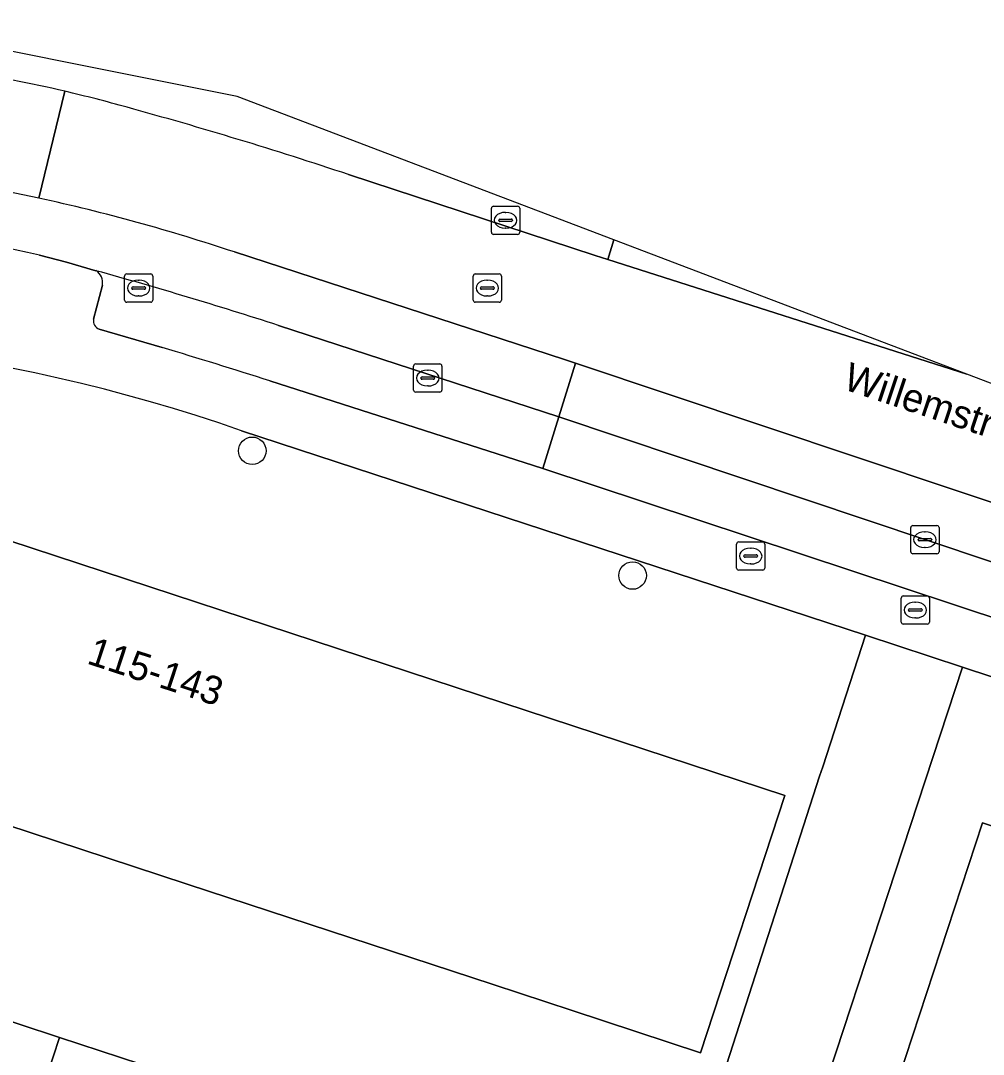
# Model space of a CAD drawing. Extents: x 159960 to 160866, y 382700 to 383354.
# Drawn here: x 160319.72 to 160353.88, y 383315.87 to 383352.54 of the extents above; entities that cross this region are included whole.
import ezdxf

# ---------------------------------------------------------------- set-up
doc = ezdxf.new("R2010")
doc.units = 0
for name, color, linetype in [('IMGEO_Boom', 7, 'Continuous'), ('IMGEO_Brandkraan', 7, 'Continuous'), ('IMGEO_Erf', 7, 'Continuous'), ('IMGEO_Kolk', 7, 'Continuous'), ('IMGEO_Openbare_ruimte_label', 7, 'Continuous'), ('IMGEO_Pand', 7, 'Continuous'), ('IMGEO_Pand_nummerreeks', 7, 'Continuous'), ('IMGEO_Parkeervlak_open', 7, 'Continuous'), ('IMGEO_Rijbaan_lokaal_gesloten', 7, 'Continuous'), ('IMGEO_Rioolput', 7, 'Continuous'), ('IMGEO_Voetpad_open', 7, 'Continuous')]:
    doc.layers.add(name, color=color, linetype=linetype)

msp = doc.modelspace()

# ---------------------------------------------------------------- linework, layer by layer
at = {"layer": 'IMGEO_Boom'}
for centre in [(160327.94, 383337.28), (160341.433, 383332.855)]:
    msp.add_circle(centre, 0.489, dxfattribs=at)
at = {"layer": 'IMGEO_Brandkraan'}
for p, q in [((160345.123, 383333.12), (160345.123, 383333.972)), ((160345.198, 383334.046), (160346.05, 383334.046)), ((160346.124, 383333.972), (160346.124, 383333.12)), ((160345.382, 383333.54), (160345.382, 383333.552)), ((160345.425, 383333.589), (160345.823, 383333.589)), ((160345.611, 383333.826), (160345.636, 383333.826)), ((160345.866, 383333.552), (160345.866, 383333.54)), ((160345.82, 383333.503), (160345.422, 383333.503)), ((160345.634, 383333.266), (160345.609, 383333.266)), ((160346.05, 383333.046), (160345.198, 383333.046)), ((160351.038, 383332.13), (160351.89, 383332.13)), ((160350.963, 383331.204), (160350.963, 383332.056)), ((160351.451, 383331.91), (160351.476, 383331.91)), ((160351.964, 383332.056), (160351.964, 383331.204)), ((160351.222, 383331.624), (160351.222, 383331.636)), ((160351.66, 383331.587), (160351.262, 383331.587)), ((160351.265, 383331.673), (160351.663, 383331.673)), ((160351.474, 383331.35), (160351.449, 383331.35)), ((160351.706, 383331.636), (160351.706, 383331.624)), ((160351.89, 383331.13), (160351.038, 383331.13))]:
    msp.add_line(p, q, dxfattribs=at)
for points in [[(160345.123, 383333.12), (160345.123, 383333.972)], [(160345.198, 383334.046), (160346.05, 383334.046)], [(160346.124, 383333.972), (160346.124, 383333.12)], [(160346.05, 383333.046), (160345.198, 383333.046)], [(160351.038, 383332.13), (160351.89, 383332.13)], [(160350.963, 383331.204), (160350.963, 383332.056)], [(160351.964, 383332.056), (160351.964, 383331.204)], [(160351.89, 383331.13), (160351.038, 383331.13)]]:
    msp.add_lwpolyline(points, dxfattribs=at)
for centre, radius, start, end in [((160345.2, 383333.97), 0.0765, 91.552, 178.448), ((160345.2, 383333.97), 0.0765, 91.552, 178.448), ((160346.048, 383333.97), 0.0765, 1.552, 88.448), ((160346.048, 383333.97), 0.0765, 1.552, 88.448), ((160345.422, 383333.549), 0.0403, 85.8775, 175.7526), ((160345.419, 383333.539), 0.0366, 178.938, 274.7102), ((160345.823, 383333.546), 0.043, 264.8664, 352.4533), ((160345.827, 383333.551), 0.0386, 1.7309, 96.639), ((160345.2, 383333.122), 0.0765, 181.552, 268.448), ((160345.2, 383333.122), 0.0765, 181.552, 268.448), ((160346.048, 383333.122), 0.0765, 271.552, 358.448), ((160346.048, 383333.122), 0.0765, 271.552, 358.448), ((160351.04, 383332.054), 0.0765, 91.552, 178.448), ((160351.04, 383332.054), 0.0765, 91.552, 178.448), ((160351.888, 383332.054), 0.0765, 1.552, 88.448), ((160351.888, 383332.054), 0.0765, 1.552, 88.448), ((160351.262, 383331.633), 0.0403, 85.8775, 175.7526), ((160351.259, 383331.623), 0.0366, 178.938, 274.7102), ((160351.663, 383331.63), 0.043, 264.8664, 352.4533), ((160351.667, 383331.635), 0.0386, 1.7309, 96.639), ((160351.04, 383331.206), 0.0765, 181.552, 268.448), ((160351.04, 383331.206), 0.0765, 181.552, 268.448), ((160351.888, 383331.206), 0.0765, 271.552, 358.448), ((160351.888, 383331.206), 0.0765, 271.552, 358.448)]:
    msp.add_arc(centre, radius, start, end, dxfattribs=at)
for centre, major_axis, ratio, start_param, end_param in [((160345.61, 383333.546), (-0.387, 0.002), 0.722429, 4.712389, 7.853982), ((160345.635, 383333.546), (-0.39, 0.002), 0.717154, 1.570796, 4.712389), ((160351.45, 383331.63), (-0.387, 0.002), 0.722429, 4.712389, 7.853982), ((160351.475, 383331.63), (-0.39, 0.002), 0.717154, 1.570796, 4.712389)]:
    msp.add_ellipse(centre, major_axis=major_axis, ratio=ratio, start_param=start_param, end_param=end_param, dxfattribs=at)
at = {"layer": 'IMGEO_Erf'}
for points in [[(160294.643, 383340.108), (160295.522, 383338.01), (160299.076, 383339.507), (160299.604, 383338.3), (160304.591, 383340.38), (160306.367, 383339.797), (160305.935, 383338.483), (160346.836, 383325.049), (160343.838, 383315.922), (160339.287, 383317.418), (160336.483, 383318.339), (160325.633, 383321.902)], [(160318.229, 383317.411), (160321.105, 383316.464), (160323.98, 383315.516), (160323.304, 383313.464), (160331.274, 383310.851), (160331.957, 383312.922), (160334.773, 383311.994), (160337.589, 383311.067), (160336.906, 383308.995), (160342.152, 383307.387), (160348.068, 383325.735), (160348.178, 383326.072), (160349.696, 383330.734), (160327.562, 383337.994)], [(160378.836, 383321.134), (160353.138, 383329.606), (160345.489, 383306.308), (160342.824, 383298.191), (160357.034, 383293.635)], [(160325.633, 383321.902), (160322.789, 383322.836), (160311.959, 383326.393)], [(160358.663, 383304.22), (160352.531, 383306.232), (160354.223, 383311.389), (160350.128, 383312.732), (160353.853, 383324.085), (160359.803, 383322.132)]]:
    msp.add_lwpolyline(points, dxfattribs=at)
msp.add_arc((160307.282, 383279.559), 61.854, 70.86077, 95.92134, dxfattribs=at)
at = {"layer": 'IMGEO_Kolk'}
for p, q in [((160323.408, 383342.627), (160323.408, 383343.479)), ((160323.483, 383343.553), (160324.335, 383343.553)), ((160324.409, 383343.479), (160324.409, 383342.627)), ((160323.71, 383343.096), (160324.108, 383343.096)), ((160323.896, 383343.333), (160323.921, 383343.333)), ((160323.667, 383343.047), (160323.667, 383343.059)), ((160324.105, 383343.01), (160323.707, 383343.01)), ((160323.919, 383342.773), (160323.894, 383342.773)), ((160324.151, 383343.059), (160324.151, 383343.047)), ((160324.335, 383342.553), (160323.483, 383342.553)), ((160333.665, 383339.435), (160333.665, 383340.287)), ((160333.74, 383340.361), (160334.592, 383340.361)), ((160334.153, 383340.141), (160334.178, 383340.141)), ((160334.666, 383340.287), (160334.666, 383339.435)), ((160333.924, 383339.855), (160333.924, 383339.867)), ((160334.362, 383339.818), (160333.964, 383339.818)), ((160333.967, 383339.904), (160334.365, 383339.904)), ((160334.408, 383339.867), (160334.408, 383339.855)), ((160334.176, 383339.581), (160334.151, 383339.581)), ((160334.592, 383339.361), (160333.74, 383339.361)), ((160351.304, 383333.701), (160351.304, 383334.553)), ((160351.379, 383334.627), (160352.231, 383334.627)), ((160351.792, 383334.407), (160351.817, 383334.407)), ((160352.305, 383334.553), (160352.305, 383333.701)), ((160351.563, 383334.121), (160351.563, 383334.133)), ((160352.001, 383334.084), (160351.603, 383334.084)), ((160351.606, 383334.17), (160352.004, 383334.17)), ((160352.047, 383334.133), (160352.047, 383334.121)), ((160352.231, 383333.627), (160351.379, 383333.627)), ((160351.815, 383333.847), (160351.79, 383333.847))]:
    msp.add_line(p, q, dxfattribs=at)
for points in [[(160323.408, 383342.627), (160323.408, 383343.479)], [(160323.483, 383343.553), (160324.335, 383343.553)], [(160324.409, 383343.479), (160324.409, 383342.627)], [(160324.335, 383342.553), (160323.483, 383342.553)], [(160333.665, 383339.435), (160333.665, 383340.287)], [(160333.74, 383340.361), (160334.592, 383340.361)], [(160334.666, 383340.287), (160334.666, 383339.435)], [(160334.592, 383339.361), (160333.74, 383339.361)], [(160351.304, 383333.701), (160351.304, 383334.553)], [(160351.379, 383334.627), (160352.231, 383334.627)], [(160352.305, 383334.553), (160352.305, 383333.701)], [(160352.231, 383333.627), (160351.379, 383333.627)]]:
    msp.add_lwpolyline(points, dxfattribs=at)
for centre, radius, start, end in [((160323.485, 383343.477), 0.0765, 91.552, 178.448), ((160323.485, 383343.477), 0.0765, 91.552, 178.448), ((160324.333, 383343.477), 0.0765, 1.552, 88.448), ((160324.333, 383343.477), 0.0765, 1.552, 88.448), ((160323.707, 383343.056), 0.0403, 85.8775, 175.7526), ((160324.112, 383343.058), 0.0386, 1.7309, 96.639), ((160323.704, 383343.046), 0.0366, 178.938, 274.7102), ((160324.108, 383343.053), 0.043, 264.8664, 352.4533), ((160323.485, 383342.629), 0.0765, 181.552, 268.448), ((160323.485, 383342.629), 0.0765, 181.552, 268.448), ((160324.333, 383342.629), 0.0765, 271.552, 358.448), ((160324.333, 383342.629), 0.0765, 271.552, 358.448), ((160333.742, 383340.285), 0.0765, 91.552, 178.448), ((160333.742, 383340.285), 0.0765, 91.552, 178.448), ((160334.59, 383340.285), 0.0765, 1.552, 88.448), ((160334.59, 383340.285), 0.0765, 1.552, 88.448), ((160333.964, 383339.864), 0.0403, 85.8775, 175.7526), ((160333.961, 383339.854), 0.0366, 178.938, 274.7102), ((160334.365, 383339.861), 0.043, 264.8664, 352.4533), ((160334.369, 383339.866), 0.0386, 1.7309, 96.639), ((160333.742, 383339.437), 0.0765, 181.552, 268.448), ((160333.742, 383339.437), 0.0765, 181.552, 268.448), ((160334.59, 383339.437), 0.0765, 271.552, 358.448), ((160334.59, 383339.437), 0.0765, 271.552, 358.448), ((160351.381, 383334.551), 0.0765, 91.552, 178.448), ((160351.381, 383334.551), 0.0765, 91.552, 178.448), ((160352.229, 383334.551), 0.0765, 1.552, 88.448), ((160352.229, 383334.551), 0.0765, 1.552, 88.448), ((160351.603, 383334.13), 0.0403, 85.8775, 175.7526), ((160351.6, 383334.12), 0.0366, 178.938, 274.7102), ((160352.004, 383334.127), 0.043, 264.8664, 352.4533), ((160352.008, 383334.132), 0.0386, 1.7309, 96.639), ((160351.381, 383333.703), 0.0765, 181.552, 268.448), ((160351.381, 383333.703), 0.0765, 181.552, 268.448), ((160352.229, 383333.703), 0.0765, 271.552, 358.448), ((160352.229, 383333.703), 0.0765, 271.552, 358.448)]:
    msp.add_arc(centre, radius, start, end, dxfattribs=at)
for centre, major_axis, ratio, start_param, end_param in [((160323.895, 383343.053), (-0.387, 0.002), 0.722429, 4.712389, 7.853982), ((160323.92, 383343.053), (-0.39, 0.002), 0.717154, 1.570796, 4.712389), ((160334.152, 383339.861), (-0.387, 0.002), 0.722429, 4.712389, 7.853982), ((160334.177, 383339.861), (-0.39, 0.002), 0.717154, 1.570796, 4.712389), ((160351.791, 383334.127), (-0.387, 0.002), 0.722429, 4.712389, 7.853982), ((160351.816, 383334.127), (-0.39, 0.002), 0.717154, 1.570796, 4.712389)]:
    msp.add_ellipse(centre, major_axis=major_axis, ratio=ratio, start_param=start_param, end_param=end_param, dxfattribs=at)
at = {"layer": 'IMGEO_Pand'}
for points in [[(160325.633, 383321.902), (160336.483, 383318.339), (160339.287, 383317.418), (160343.838, 383315.922), (160346.836, 383325.049), (160305.935, 383338.483), (160306.367, 383339.797), (160304.591, 383340.38), (160299.604, 383338.3), (160299.076, 383339.507), (160295.522, 383338.01), (160298.514, 383330.809), (160300.173, 383326.818), (160301.78, 383327.486), (160302.447, 383329.517), (160309.145, 383327.317), (160311.959, 383326.393), (160322.789, 383322.836)], [(160367.853, 383319.496), (160362.166, 383321.362), (160362.613, 383322.723), (160360.251, 383323.498), (160359.803, 383322.132), (160353.853, 383324.085), (160350.128, 383312.732), (160354.223, 383311.389), (160352.531, 383306.232), (160358.663, 383304.22), (160360.348, 383309.355), (160364.119, 383308.118)], [(160320.428, 383314.411), (160321.105, 383316.464), (160318.229, 383317.411), (160317.553, 383315.358), (160317.979, 383315.218)], [(160320.428, 383314.411), (160323.304, 383313.464), (160323.98, 383315.516), (160321.105, 383316.464)]]:
    msp.add_lwpolyline(points, close=True, dxfattribs=at)
at = {"layer": 'IMGEO_Parkeervlak_open'}
for points in [[(160322.621, 383343.155), (160322.306, 383341.946)], [(160328.565, 383339.757), (160338.251, 383336.653), (160338.82, 383338.484), (160328.868, 383341.729)], [(160322.509, 383341.595), (160324.74, 383340.94)], [(160338.82, 383338.484), (160338.251, 383336.653), (160374.891, 383324.523), (160380.694, 383322.786)], [(160384.122, 383323.645), (160378.569, 383325.322), (160373.295, 383327.021), (160365.039, 383329.703), (160338.82, 383338.484)]]:
    msp.add_lwpolyline(points, dxfattribs=at)
for centre, radius, start, end in [((160322.122, 383343.243), 0.507, 349.9998, 57.6776), ((160279.47, 383188.792), 160.717, 72.09976, 74.50987), ((160322.623, 383341.895), 0.321, 170.863, 249.2227), ((160282.953, 383199.055), 147.911, 72.03867, 73.58964)]:
    msp.add_arc(centre, radius, start, end, dxfattribs=at)
at = {"layer": 'IMGEO_Rijbaan_lokaal_gesloten'}
for points in [[(160340.77, 383344.767), (160327.403, 383349.855), (160313.978, 383352.541), (160313.822, 383351.21)], [(160320.361, 383346.246), (160321.29, 383350.035)], [(160321.29, 383350.035), (160320.361, 383346.246)], [(160331.355, 383347.08), (160340.11, 383344.205), (160340.552, 383344.064), (160340.77, 383344.767)], [(160353.298, 383339.998), (160340.552, 383344.064), (160340.11, 383344.205), (160331.355, 383347.08)], [(160353.298, 383339.998), (160340.77, 383344.767), (160340.552, 383344.064), (160353.298, 383339.998)], [(160320.391, 383344.223), (160321.349, 383343.977), (160322.393, 383343.671)], [(160328.868, 383341.729), (160338.82, 383338.484), (160339.411, 383340.388), (160339.019, 383340.519), (160327.31, 383344.334)], [(160327.31, 383344.334), (160339.019, 383340.519), (160339.411, 383340.388), (160379.541, 383326.968), (160386.351, 383324.937), (160393.65, 383323.244), (160405.05, 383321.475), (160422.132, 383319.19), (160421.928, 383317.329), (160422.565, 383317.249), (160422.888, 383317.208), (160423.763, 383317.136), (160424.079, 383322.77), (160418.682, 383323.85)], [(160339.411, 383340.388), (160338.82, 383338.484), (160365.039, 383329.703), (160373.295, 383327.021), (160378.569, 383325.322), (160384.122, 383323.645)], [(160395.778, 383321.003), (160402.357, 383319.894), (160407.261, 383319.183), (160408.466, 383319.025), (160412.174, 383318.537), (160413.297, 383318.401), (160414.421, 383318.272), (160421.928, 383317.329), (160422.132, 383319.19), (160405.05, 383321.475), (160393.65, 383323.244), (160386.351, 383324.937), (160379.541, 383326.968), (160339.411, 383340.388)], [(160410.425, 383325.501), (160405.947, 383326.397), (160405.882, 383325.735), (160401.333, 383326.227), (160394.038, 383327.743), (160387.808, 383329.096), (160379.561, 383331.676), (160370.285, 383333.532), (160353.298, 383339.998)]]:
    msp.add_lwpolyline(points, dxfattribs=at)
for centre, radius, start, end in [((160309.575, 383299.896), 51.49, 76.8485, 85.2685), ((160309.575, 383299.896), 51.49, 76.8485, 85.2685), ((160309.96, 383301.404), 49.933, 74.2729, 76.8856), ((160309.96, 383301.404), 49.933, 74.2729, 76.8856), ((160283.171, 383202.613), 152.291, 71.55485, 74.64583), ((160283.171, 383202.613), 152.291, 71.55485, 74.64583), ((160305.485, 383278.481), 69.378, 77.61852, 85.19699), ((160305.485, 383278.481), 69.378, 77.61852, 85.19699), ((160305.57, 383278.904), 68.947, 71.61987, 77.61191), ((160305.57, 383278.904), 68.947, 71.61987, 77.61191), ((160304.506, 383274.704), 71.311, 77.12925, 88.46226), ((160279.47, 383188.792), 160.717, 72.09976, 74.50987)]:
    msp.add_arc(centre, radius, start, end, dxfattribs=at)
at = {"layer": 'IMGEO_Rioolput'}
for p, q in [((160336.426, 383345.033), (160336.426, 383345.885)), ((160336.501, 383345.959), (160337.353, 383345.959)), ((160336.914, 383345.739), (160336.939, 383345.739)), ((160337.427, 383345.885), (160337.427, 383345.033)), ((160336.685, 383345.453), (160336.685, 383345.465)), ((160337.123, 383345.416), (160336.725, 383345.416)), ((160336.728, 383345.502), (160337.126, 383345.502)), ((160337.169, 383345.465), (160337.169, 383345.453)), ((160337.353, 383344.959), (160336.501, 383344.959)), ((160336.937, 383345.179), (160336.912, 383345.179)), ((160335.778, 383342.627), (160335.778, 383343.479)), ((160335.853, 383343.553), (160336.705, 383343.553)), ((160336.779, 383343.479), (160336.779, 383342.627)), ((160336.08, 383343.096), (160336.478, 383343.096)), ((160336.266, 383343.333), (160336.291, 383343.333)), ((160336.037, 383343.047), (160336.037, 383343.059)), ((160336.475, 383343.01), (160336.077, 383343.01)), ((160336.289, 383342.773), (160336.264, 383342.773)), ((160336.521, 383343.059), (160336.521, 383343.047)), ((160336.705, 383342.553), (160335.853, 383342.553))]:
    msp.add_line(p, q, dxfattribs=at)
for points in [[(160336.426, 383345.033), (160336.426, 383345.885)], [(160336.501, 383345.959), (160337.353, 383345.959)], [(160337.427, 383345.885), (160337.427, 383345.033)], [(160337.353, 383344.959), (160336.501, 383344.959)], [(160335.778, 383342.627), (160335.778, 383343.479)], [(160335.853, 383343.553), (160336.705, 383343.553)], [(160336.779, 383343.479), (160336.779, 383342.627)], [(160336.705, 383342.553), (160335.853, 383342.553)]]:
    msp.add_lwpolyline(points, dxfattribs=at)
for centre, radius, start, end in [((160336.503, 383345.883), 0.0765, 91.552, 178.448), ((160336.503, 383345.883), 0.0765, 91.552, 178.448), ((160337.351, 383345.883), 0.0765, 1.552, 88.448), ((160337.351, 383345.883), 0.0765, 1.552, 88.448), ((160336.725, 383345.462), 0.0403, 85.8775, 175.7526), ((160336.722, 383345.452), 0.0366, 178.938, 274.7102), ((160337.126, 383345.459), 0.043, 264.8664, 352.4533), ((160337.13, 383345.464), 0.0386, 1.7309, 96.639), ((160336.503, 383345.035), 0.0765, 181.552, 268.448), ((160336.503, 383345.035), 0.0765, 181.552, 268.448), ((160337.351, 383345.035), 0.0765, 271.552, 358.448), ((160337.351, 383345.035), 0.0765, 271.552, 358.448), ((160335.855, 383343.477), 0.0765, 91.552, 178.448), ((160335.855, 383343.477), 0.0765, 91.552, 178.448), ((160336.703, 383343.477), 0.0765, 1.552, 88.448), ((160336.703, 383343.477), 0.0765, 1.552, 88.448), ((160336.077, 383343.056), 0.0403, 85.8775, 175.7526), ((160336.482, 383343.058), 0.0386, 1.7309, 96.639), ((160336.074, 383343.046), 0.0366, 178.938, 274.7102), ((160336.478, 383343.053), 0.043, 264.8664, 352.4533), ((160335.855, 383342.629), 0.0765, 181.552, 268.448), ((160335.855, 383342.629), 0.0765, 181.552, 268.448), ((160336.703, 383342.629), 0.0765, 271.552, 358.448), ((160336.703, 383342.629), 0.0765, 271.552, 358.448)]:
    msp.add_arc(centre, radius, start, end, dxfattribs=at)
for centre, major_axis, ratio, start_param, end_param in [((160336.913, 383345.459), (-0.387, 0.002), 0.722429, 4.712389, 7.853982), ((160336.938, 383345.459), (-0.39, 0.002), 0.717154, 1.570796, 4.712389), ((160336.265, 383343.053), (-0.387, 0.002), 0.722429, 4.712389, 7.853982), ((160336.29, 383343.053), (-0.39, 0.002), 0.717154, 1.570796, 4.712389)]:
    msp.add_ellipse(centre, major_axis=major_axis, ratio=ratio, start_param=start_param, end_param=end_param, dxfattribs=at)
at = {"layer": 'IMGEO_Voetpad_open'}
for points in [[(160322.393, 383343.671), (160321.349, 383343.977), (160320.391, 383344.223)], [(160322.306, 383341.946), (160322.621, 383343.155)], [(160324.74, 383340.94), (160322.509, 383341.595)], [(160338.251, 383336.653), (160328.565, 383339.757)], [(160327.562, 383337.994), (160349.696, 383330.734), (160353.138, 383329.606), (160378.836, 383321.134), (160382.972, 383319.807), (160386.792, 383318.704), (160390.43, 383317.329), (160394.323, 383315.825), (160397.451, 383314.436), (160399.782, 383313.197), (160402.42, 383311.607), (160404.287, 383310.442), (160405.453, 383309.675), (160406.277, 383309.095), (160407.85, 383307.867), (160409.42, 383306.607), (160410.927, 383305.287), (160411.638, 383304.574), (160412.947, 383303.057), (160414.865, 383300.708), (160416.978, 383298.12), (160425.599, 383307.806)], [(160380.694, 383322.786), (160374.891, 383324.523), (160338.251, 383336.653)]]:
    msp.add_lwpolyline(points, dxfattribs=at)
msp.add_lwpolyline([(160353.138, 383329.606), (160349.696, 383330.734), (160348.178, 383326.072), (160348.068, 383325.735), (160342.152, 383307.387), (160341.236, 383304.766), (160339.462, 383299.288), (160342.824, 383298.191), (160345.489, 383306.308)], close=True, dxfattribs=at)
for centre, radius, start, end in [((160304.506, 383274.704), 71.311, 77.12925, 88.46226), ((160322.122, 383343.243), 0.507, 349.9998, 57.6776), ((160322.623, 383341.895), 0.321, 170.863, 249.2227), ((160307.282, 383279.559), 61.854, 70.86077, 95.92134), ((160282.953, 383199.055), 147.911, 72.03867, 73.58964)]:
    msp.add_arc(centre, radius, start, end, dxfattribs=at)

# ---------------------------------------------------------------- texts
at = {"layer": 'IMGEO_Openbare_ruimte_label'}
msp.add_text('Willemstraat', height=1, rotation=341.5107, dxfattribs=at).set_placement((160348.852, 383339.484))
at = {"layer": 'IMGEO_Pand_nummerreeks'}
msp.add_text('115-143', height=1, rotation=341.8171, dxfattribs=at).set_placement((160322.032, 383329.744))

doc.saveas('drawing.dxf')
